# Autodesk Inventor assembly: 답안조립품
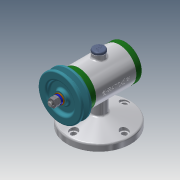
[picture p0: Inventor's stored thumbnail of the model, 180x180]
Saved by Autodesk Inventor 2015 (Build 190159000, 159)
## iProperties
Created: 2018-12
Part Number: 답안조립품
Document SubType Name: Assembly
Designer: now
Author: now
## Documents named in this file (15)
- C:\Users\now\Desktop\481207V1051\답안조립품.iam
- C:\Users\now\Desktop\481207V1051\V벨트풀리.ipt
- C:\Users\now\Desktop\481207V1051\고무캡.ipt
- C:\Users\now\Desktop\481207V1051\너트 M8.ipt
- 너트 M8.ipt
- C:\Users\now\Desktop\481207V1051\뒤커버.ipt
- C:\Users\now\Desktop\481207V1051\베어링 15 x 32 x 9.ipt
- C:\Users\now\Desktop\481207V1051\본체.ipt
- C:\Users\now\Desktop\481207V1051\볼트 M4 x 12.ipt
- C:\Users\now\Desktop\481207V1051\스프링와셔 8.ipt
- C:\Users\now\Desktop\481207V1051\앞커버.ipt
- C:\Users\now\Desktop\481207V1051\오일 실 15 25 7.ipt
- C:\Users\now\Desktop\481207V1051\와셔 8x17.ipt
- C:\Users\now\Desktop\481207V1051\축.ipt
- C:\Users\now\Desktop\481207V1051\키 3 x 3 x 12.ipt
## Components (2 placed, 2 different names)
1. V벨트풀리:1 — 각도:2
2. 고무캡:1
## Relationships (1: Angle 1)
- 각도:2 [Angle]: V벨트풀리:1
